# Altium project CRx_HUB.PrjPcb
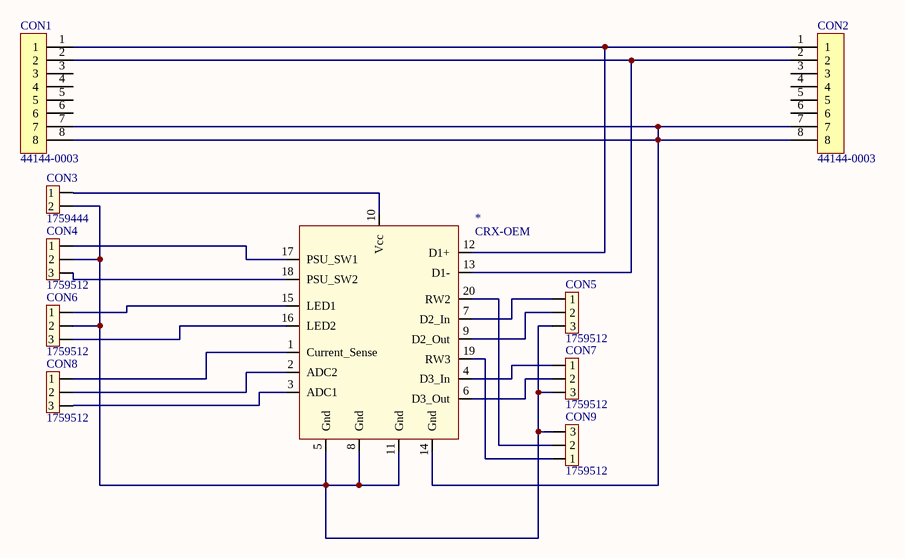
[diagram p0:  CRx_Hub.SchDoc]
1 sheet, 10 parts. Net scope: global (net labels, ports and power ports of the same name join across sheets).
Board file:  CRx_Hub.PcbDoc

## Sheet  CRx_Hub.SchDoc
size A4; SheetNumber: 1; SheetTotal: 1

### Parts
*  CRX-OEM  [CRX_OEM-THRU]
CON1  44144-0003  [44144_0003]
CON2  44144-0003  [44144_0003]
CON3  1759444  [MSTBA2]
CON4  1759512  [MSTB 2,5/ 3-G-5,08 BK]
CON5  1759512  [MSTB 2,5/ 3-G-5,08 BK]
CON6  1759512  [MSTB 2,5/ 3-G-5,08 BK]
CON7  1759512  [MSTB 2,5/ 3-G-5,08 BK]
CON8  1759512  [MSTB 2,5/ 3-G-5,08 BK]
CON9  1759512  [MSTB 2,5/ 3-G-5,08 BK]

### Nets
Net*_1: *.1(Current_Sense) CON8.1
Net*_2: *.2(ADC2) CON8.2
Net*_3: *.3(ADC1) CON8.3
Net*_4: *.4(D3_In) CON7.1
Net*_5: *.5(Gnd) *.8(Gnd) *.11(Gnd) CON3.2 CON4.2 CON5.3 CON6.2 CON7.3 CON9.3
Net*_6: *.6(D3_Out) CON7.2
Net*_7: *.7(D2_In) CON5.1
Net*_9: *.9(D2_Out) CON5.2
Net*_10: *.10(Vcc) CON3.1
Net*_12: *.12(D1+) CON1.1 CON2.1
Net*_13: *.13(D1-) CON1.2 CON2.2
Net*_14: *.14(Gnd) CON1.7 CON1.8 CON2.7 CON2.8
Net*_15: *.15(LED1) CON6.1
Net*_16: *.16(LED2) CON6.3
Net*_17: *.17(PSU_SW1) CON4.1
Net*_18: *.18(PSU_SW2) CON4.3
Net*_19: *.19(RW3) CON9.1
Net*_20: *.20(RW2) CON9.2

Not connected (* = marked no-connect by the designer): CON1 3 4 5 6; CON2 3 4 5 6

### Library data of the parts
* = CRX-OEM: CRX OEM module
CON1 CON2 = 44144_0003: Modular Connector, RJ45, Jack, 8 Contacts, 8 Ways, 44144 Series, Cat3; Manufacturer 1: Molex; UL Certification: E107635
CON3 = MSTB 2,5/ 2-G-5,08 BK: Pluggable Terminal Blocks 2 Pos 5.08mm pitch Through Hole Header; Manufacturer 1: Phoenix Contact
CON4-CON9 = MSTB 2,5/ 3-G-5,08 BK: PCB headers, nominal current: 12 A, rated voltage (III/2): 320 V, number of positions: 3, pitch: 5.08 mm, color: black, contact surface: Tin, mounting: Wave soldering; Manufacturer 1: Phoenix Contact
